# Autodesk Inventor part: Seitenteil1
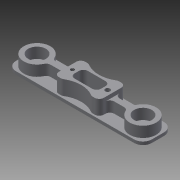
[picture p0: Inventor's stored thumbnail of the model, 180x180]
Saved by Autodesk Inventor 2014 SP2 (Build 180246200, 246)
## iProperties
Created: 2015-04
Part Number: Seitenteil1
Material: Generisch
Document SubType Name: Modeling
Designer: e_krauts
Density: 1 g/cm^3
Appearance: Vorgabe
Mass: 43.9253 g
Surface Area: 202.838 cm^2
Volume: 43.9253 cm^3
Author: e_krauts
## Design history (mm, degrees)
sketch "Skizze1"
  geometry: L1 (0, 0)-(154, 0); L2 (154, 0)-(154, 34); L3 (154, 34)-(0, 34); L4 (0, 34)-(0, 0)
  constraints: 8 end point, 2 parallel, 1 horizontal, 1 perpendicular
  dimensions: "d0" = 154 distance of L3.end L2.end; "d1" = 34 distance between parallel lines of L3 L1
extrude "Extrusion1" new body sketch "Skizze1" distance "d2" = 3.5; taper "d3" = 0 deg
sketch "Skizze2"
  geometry: L1 (0, 0)-(154, 0) reference; L2 (154, 0)-(154, 34) reference; L3 (154, 34)-(0, 34) reference; L4 (0, 34)-(0, 0) reference; L5 (77, 34)-(77, 0); L6 (0, 17)-(154, 17); L7 (77, 20)-(35.33, 20); L8 (77, 14)-(35.33, 14); L9 (77, 20)-(118.67, 20); L10 (77, 14)-(118.67, 14); L11 (154, 17)-(0, 17); A1 r 5 centre (35.33, 25) between (30.748, 23) and (35.33, 20); A2 r 15 centre (17, 17) between (30.748, 23) and (2, 17); A3 r 5 centre (35.33, 9) between (35.33, 14) and (30.748, 11); A4 r 15 centre (17, 17) between (2, 17) and (30.748, 11); A5 r 5 centre (118.67, 25) between (118.67, 20) and (123.252, 23); A6 r 15 centre (137, 17) between (123.252, 11) and (152, 17); A7 r 15 centre (137, 17) between (152, 17) and (123.252, 23); A8 r 5 centre (118.67, 9) between (123.252, 11) and (118.67, 14)
  constraints: 16 point on circle, 14 end point, 14 symmetric about line, 8 centre point, 5 point on line, 4 midpoint, 2 tangent, 1 parallel, 6 other
  dimensions: "d4" = 6 diameter of L7 L6; "d5" = 15 radius of A2; "d6" = 120 diameter of A2.centre L5; "d7" = 5 radius of A1
extrude "Extrusion2" join sketch "Skizze2" distance "d8" = 12; taper "d9" = 0 deg
sketch "Skizze3"
  geometry: A1 r 15 centre (17, 17) between (30.748, 23) and (30.748, 11) reference; A2 r 15 centre (137, 17) between (123.252, 11) and (123.252, 23) reference; 3 further points
  constraints: 2 coincident
hole "Bohrung1" sketch "Skizze3" at (17, 17), (137, 17) diameter "d10" = 20; stored, may be unused: countersink angle "d14" = 90 deg, drill point angle "d16" = 0 deg; dims "d11" = 6, "d12" = 4, "d13" = 2, "d15" = 12
fillet "Rundung1" dims "d17" = 10
sketch "Skizze4"
  geometry: L1 (144, 34)-(10, 34) reference; L2 (0, 24)-(0, 10) reference; L3 (10, 0)-(144, 0) reference; L4 (154, 10)-(154, 24) reference; L5 (77, 34)-(77, 0); L6 (0, 17)-(154, 17); L7 (102.5, 32)-(51.5, 32); L8 (51.5, 32)-(51.5, 2); L9 (51.5, 2)-(102.5, 2); L10 (102.5, 2)-(102.5, 32); L11 (102.5, 32)-(51.5, 2); L12 (51.5, 32)-(102.5, 2); 2 further points
  constraints: 16 end point, 7 midpoint, 2 parallel, 1 horizontal, 1 perpendicular
  dimensions: "d18" = 51 distance of L9.end L8.end; "d19" = 30 distance of L8.end L7.end
extrude "Extrusion3" join sketch "Skizze4" distance "d20" = 16.5; taper "d21" = 0 deg
fillet "Rundung2" dims "d22" = 5
sketch "Skizze5"
  geometry: L1 (62, 24.5)-(92, 24.5); L2 (92, 24.5)-(92, 9.5); L3 (92, 9.5)-(62, 9.5); L4 (62, 9.5)-(62, 24.5); L5 (62, 24.5)-(92, 9.5); L6 (92, 24.5)-(62, 9.5); 2 further points
  constraints: 12 end point, 2 midpoint, 2 parallel, 1 horizontal, 1 perpendicular
  dimensions: "d23" = 30 distance of L2.end L3.end; "d24" = 15 distance of L1.end L2.end
extrude "Extrusion4" cut sketch "Skizze5" distance "d25" = 16.5; taper "d26" = 0 deg
fillet "Rundung3" dims "d27" = 5
sketch "Skizze6"
  geometry: L1 (51.5, 27)-(51.5, 7) reference; L2 (56.5, 2)-(97.5, 2) reference; L3 (102.5, 7)-(102.5, 27) reference; L4 (97.5, 32)-(56.5, 32) reference; L5 (51.5, 17)-(102.5, 17); L6 (77, 32)-(77, 2); L7 (60.417, 32)-(93.583, 32); L8 (60.417, 2)-(93.583, 2); A1 r 30 centre (77, 57) between (60.417, 32) and (93.583, 32); A2 r 30 centre (77, -23) between (93.583, 2) and (60.417, 2); 1 further point
  constraints: 8 end point, 4 midpoint, 4 point on circle, 3 symmetric about line, 2 centre point, 2 point on line, 1 collinear, 1 other
  dimensions: "d30" = 80 diameter of A1.centre L5; "d31" = 30 radius of A1
extrude "Extrusion5" cut sketch "Skizze6" distance "d32" = 16.5; taper "d33" = 0 deg
fillet "Rundung4" dims "d34" = 5
sketch "Skizze7"
  geometry: L1 (51.5, 27)-(51.5, 7) reference; L2 (102.5, 7)-(102.5, 27) reference; L3 (51.5, 17)-(102.5, 17); L4 (77, 27)-(77, 7); A1 r 30 centre (77, -23) between (92.452, 2.714) and (61.548, 2.714) reference; A2 r 30 centre (77, 57) between (61.548, 31.286) and (92.452, 31.286) reference; 3 further points
  constraints: 4 end point, 2 midpoint, 2 point on circle, 1 point on line, 1 symmetric about line
hole "Bohrung2" sketch "Skizze7" diameter "d36" = 4.134; stored, may be unused: countersink angle "d40" = 90 deg, drill point angle "d42" = 118 deg; dims "d37" = 14, "d38" = 4, "d39" = 2, "d41" = 17
sketch "Skizze9"
  geometry: C1 r 5.2 at (0, 0) reference; 2 further points
  constraints: 1 coincident
hole "Bohrung4" sketch "Skizze9" diameter "d61" = 5.5; stored, may be unused: countersink angle "d65" = 90 deg, drill point angle "d67" = 118 deg; dims "d62" = 6, "d63" = 10.4, "d64" = 2, "d66" = 8
node "Volumenkörper1"
hole "Bohrung3" diameter "d54" = 10.4; stored, may be unused: countersink angle "d58" = 90 deg, drill point angle "d60" = 0 deg; dims "d52" = 17, "d53" = 57, "d55" = 6, "d56" = 4, "d57" = 2, "d59" = 0.5
